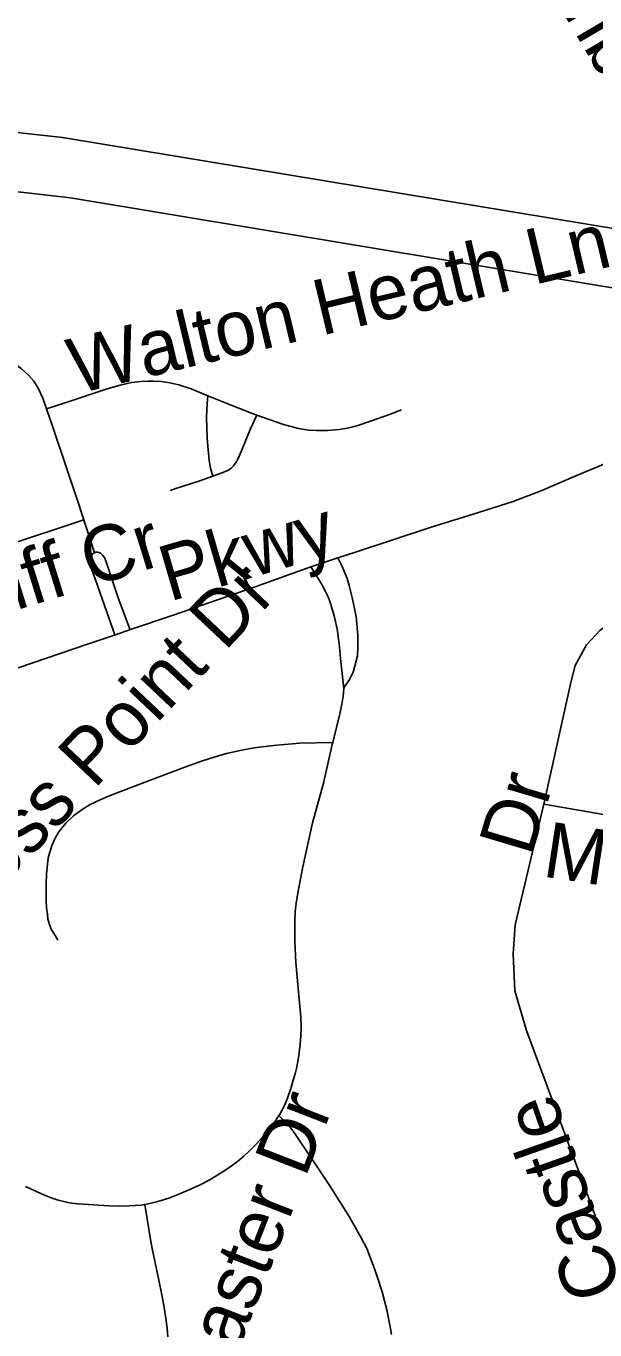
# Model space of a CAD drawing. Extents: x 1383679 to 1536984, y 460658 to 651027.
# Drawn here: x 1460933 to 1461906, y 480927 to 483158 of the extents above; entities that cross this region are included whole.
import ezdxf

# ---------------------------------------------------------------- set-up
doc = ezdxf.new("R2010")
doc.units = 0
for name, color, linetype in [('Exist Road Non-System Type 51', 7, 'Continuous'), ('Exist Road Non-System Type 51 Label', 7, 'Continuous'), ('Exist Road Primary Interstate Divided Center Attributed', 7, 'Continuous'), ('Exist Road Secondary Type 51 Attributed', 7, 'Continuous'), ('Exist Road Secondary Type 51 Label', 7, 'Continuous')]:
    doc.layers.add(name, color=color, linetype=linetype)

msp = doc.modelspace()

# ---------------------------------------------------------------- linework, layer by layer
at = {"layer": 'Exist Road Non-System Type 51'}
for points in [[(1460967.8, 482502.9), (1460961.4, 482521.3), (1460953.6, 482538.2), (1460945.8, 482550.2), (1460936.8, 482560.8), (1460925.1, 482571.5), (1460913.4, 482580.1), (1460905.8, 482584.1), (1460896.8, 482587.9), (1460886.4, 482591.3), (1460871.3, 482595), (1460845.3, 482600.2), (1460804.4, 482606.4), (1460775.1, 482610.2), (1460755.7, 482611.3), (1460740.7, 482610.6), (1460722.6, 482608.3), (1460702.6, 482604.4), (1460682.3, 482598.9), (1460672.8, 482594.4)], [(1461243.8, 482525.5), (1461226, 482532.8), (1461215.4, 482537.2), (1461194.2, 482543.9), (1461178.8, 482547.5), (1461163.7, 482549.8), (1461150.7, 482550.5), (1461141, 482550.6), (1461129.5, 482549.9), (1461113.2, 482547.8), (1461093.9, 482543.6), (1461073.5, 482538), (1460999.4, 482513.5), (1460967.8, 482502.9)], [(1461252.1, 482387.8), (1461248.4, 482401.7), (1461246.2, 482414.8), (1461243.6, 482439.3), (1461242.9, 482453.1), (1461241.8, 482488.5), (1461242.8, 482512.2), (1461243.8, 482525.5)], [(1461327.6, 482492.3), (1461321.2, 482494.5), (1461278.2, 482511.3), (1461243.8, 482525.5)], [(1461049.7, 482256.6), (1461021.7, 482342.8), (1460978.5, 482471.7), (1460967.8, 482502.9)], [(1461327.6, 482492.3), (1461316, 482467.5), (1461301.7, 482431.3), (1461294.9, 482416.6), (1461290.9, 482410), (1461287.2, 482405.1), (1461283.5, 482401.3), (1461279, 482398.2), (1461272.6, 482395.2), (1461252.1, 482387.8)], [(1461575.2, 482501.2), (1461554.7, 482493.5), (1461522.3, 482481.7), (1461500.7, 482474.7), (1461491.7, 482471.9), (1461482.9, 482469.9), (1461468.8, 482467.6), (1461448.6, 482465.9), (1461429.8, 482465.9), (1461415.9, 482466.5), (1461398.9, 482469.4), (1461373.2, 482476.3), (1461327.6, 482492.3)], [(1461252.1, 482387.8), (1461228.6, 482379.4), (1461189.2, 482366.6), (1461179.3, 482363.3)], [(1461031.4, 482313), (1460999, 482302), (1460924.9, 482277.6), (1460872.1, 482261), (1460851.8, 482253.4)], [(1461049.7, 482256.6), (1461048.6, 482256.1), (1461047.8, 482255.5), (1461046.6, 482254.6), (1461045.4, 482253), (1461044.5, 482251.5), (1461043.5, 482249.3), (1461042.7, 482245.4), (1461042.2, 482241.1), (1461042.6, 482237.7), (1461045, 482229.4), (1461050.8, 482212.3), (1461067.1, 482166.4), (1461084.7, 482116.1)], [(1461110.8, 482124.9), (1461090.7, 482178.1), (1461068.2, 482246.2), (1461066.3, 482249.4), (1461064.2, 482252), (1461061.4, 482254.9), (1461060.1, 482256), (1461058.8, 482256.6), (1461057, 482257.1), (1461055.4, 482257.4), (1461053.8, 482257.5), (1461052.4, 482257.4), (1461050.9, 482257.1), (1461049.7, 482256.6)], [(1461476.6, 482025.6), (1461486.4, 482039.8), (1461492.5, 482052.6), (1461497.2, 482069.4), (1461499.8, 482080.1), (1461500.8, 482095.8), (1461500.6, 482115.7), (1461497.4, 482147.4), (1461490.6, 482180.1), (1461485.7, 482200.7), (1461482.1, 482212.4), (1461473.6, 482233.4), (1461466.3, 482247.8)], [(1461419.9, 482232.7), (1461432.6, 482212.4), (1461438.2, 482203.7), (1461441.4, 482198), (1461445.2, 482190.6), (1461448.5, 482183.4), (1461451.4, 482176.6), (1461454.1, 482168.4), (1461457.2, 482158.7), (1461460.1, 482148.5), (1461462.2, 482139.3), (1461463.9, 482131.2), (1461465.5, 482122.8), (1461467, 482112.6), (1461468.4, 482100.8), (1461469.7, 482089.6), (1461471.1, 482075.9), (1461476.7, 482024.2), (1461475.7, 482011.3), (1461473.4, 481997.4), (1461469.7, 481980.9), (1461457.6, 481932)], [(1461819.1, 481826.7), (1461865.1, 482034.8), (1461872.4, 482063.7), (1461891.9, 482099.3), (1461915.4, 482124.1), (1461936.5, 482140.3), (1461954.6, 482152.3), (1461974.1, 482158.4), (1461995.6, 482163.8), (1462030.5, 482162.4), (1462058.7, 482157.7), (1462276.8, 482075.1)], [(1461457.6, 481932), (1461401.4, 481930.8), (1461362.1, 481927.5), (1461322.6, 481922.7), (1461299.2, 481918.4), (1461275.8, 481913.2), (1461254.6, 481907.1), (1461234.5, 481900.3), (1461208.8, 481891.3), (1461148.7, 481868.9), (1461099.1, 481849.7), (1461073.6, 481840.2), (1461059.3, 481833.9), (1461042.2, 481825.8), (1461028.6, 481817.5), (1461014.7, 481807), (1461000.9, 481794.1), (1460988.8, 481778.8), (1460982.3, 481768.2), (1460977.5, 481756.9), (1460972.7, 481742.5), (1460970.7, 481734.5), (1460969.2, 481722.9), (1460967.9, 481707.3), (1460966.9, 481689.2), (1460967, 481661.3), (1460967.9, 481648.9), (1460969.2, 481637.9), (1460970.2, 481629.8), (1460973.2, 481618.5), (1460976.5, 481611.2), (1460982.3, 481601.6), (1460987.1, 481593.6)], [(1461457.6, 481932), (1461456.7, 481928.4), (1461441.5, 481862.6), (1461423.2, 481794.6), (1461406.5, 481719.1), (1461397.8, 481674.6), (1461394.8, 481657), (1461393.1, 481642.2), (1461392.6, 481626.3), (1461392.9, 481592), (1461394.7, 481555.3), (1461398.8, 481505.4), (1461402.7, 481461.8), (1461403.6, 481444.6), (1461403.2, 481430.1), (1461402.1, 481416.4), (1461400.1, 481400.8), (1461398.4, 481389.3), (1461395.3, 481374.2), (1461393.1, 481364.9), (1461390, 481353.8), (1461385.8, 481339.9), (1461380.2, 481323.3), (1461375.4, 481312), (1461370.7, 481301.9), (1461366.4, 481294.9), (1461365.4, 481293.4)], [(1461907.1, 481120.6), (1461789.1, 481438.9), (1461769.2, 481507), (1461766.2, 481570.5), (1461769.9, 481619.8), (1461819.1, 481826.7)], [(1461819.1, 481826.7), (1461967.4, 481800.8), (1462263.3, 481754.2)], [(1461365.4, 481293.4), (1461358.8, 481283.3), (1461351.3, 481273), (1461344.7, 481265), (1461338.2, 481256.9), (1461326.4, 481244.3), (1461314.5, 481232.7), (1461305.5, 481223.9), (1461294.4, 481214.6), (1461283.8, 481206.8), (1461271, 481198.3), (1461256.6, 481189), (1461246.1, 481183.2), (1461230.5, 481174.9), (1461214.1, 481167.3), (1461194, 481158.8), (1461176.8, 481152.2), (1461164, 481148.2), (1461156.2, 481145.9), (1461146.7, 481143.3), (1461138.6, 481141.7), (1461135.9, 481141.2)], [(1461365.4, 481293.4), (1461382.4, 481276.7), (1461392.5, 481262.9), (1461452.7, 481173.4), (1461485.9, 481120.5), (1461506.2, 481084.4), (1461515.7, 481066), (1461526.6, 481037.4), (1461534.4, 481016.3), (1461542.2, 480992), (1461550.1, 480961), (1461556.1, 480932.2), (1461558.1, 480918.7)], [(1461135.9, 481141.2), (1461130.3, 481140.2), (1461119.7, 481139.4), (1461109.9, 481139.1), (1461091.8, 481138.6), (1461075.2, 481139.1), (1461056.8, 481139.9), (1461030.9, 481141.7), (1461020.8, 481142.4), (1461006.7, 481144.4), (1460997.4, 481146.2), (1460987.6, 481148.7), (1460977.5, 481152.2), (1460964.4, 481157.5), (1460931.8, 481172.3)], [(1461135.9, 481141.2), (1461145, 481084.6), (1461148.7, 481066), (1461159.5, 481014.9), (1461165.8, 480983.7), (1461169.1, 480965), (1461172.1, 480946.1), (1461174.4, 480929.5), (1461175.2, 480914.6)]]:
    msp.add_lwpolyline(points, dxfattribs=at)
at = {"layer": 'Exist Road Primary Interstate Divided Center Attributed'}
for points in [[(1462470, 482723.8), (1460995.2, 482967.2), (1459214, 483163.4), (1458773.1, 483198.7), (1458336.5, 483234.1), (1458156.8, 483240.7)], [(1458190, 483136.4), (1458674, 483131), (1461008.7, 482864.3), (1463176.2, 482504.4), (1464881.1, 482241.3), (1465669.4, 482116.9), (1466817.1, 481926.4), (1467830.4, 481763.9), (1468861.2, 481599.9)]]:
    msp.add_lwpolyline(points, dxfattribs=at)
at = {"layer": 'Exist Road Secondary Type 51 Attributed'}
for p, q in [((1461466.3, 482247.8), (1461419.9, 482232.7)), ((1461111.5, 482125.1), (1461085.6, 482116.4))]:
    msp.add_line(p, q, dxfattribs=at)
for points in [[(1462020.9, 482456.9), (1461991.3, 482442.2), (1461948.6, 482421.9), (1461917.3, 482406.7), (1461873.6, 482388.5), (1461815.3, 482363.3), (1461766.2, 482344.4), (1461706.9, 482325.4), (1461624.4, 482299.9), (1461498, 482258.1), (1461466.3, 482247.8)], [(1461419.9, 482232.7), (1461324.7, 482198.1), (1461184.4, 482149.7), (1461111.5, 482125.1)], [(1461085.6, 482116.4), (1461036.4, 482099.9), (1460827, 482028.4), (1460597.2, 481949.9), (1460506.1, 481919.8), (1460303.2, 481853.2), (1460125.7, 481792.9), (1459950.5, 481735), (1459913.9, 481724)]]:
    msp.add_lwpolyline(points, dxfattribs=at)

# ---------------------------------------------------------------- texts
at = {"layer": 'Exist Road Non-System Type 51 Label'}
for s, rotation, p in [('Brambleton Ct', 300.4411, (1461731.5, 483385.1)), ('Walton Heath Ln', 13.4254, (1461018.7, 482528)), ('Baniff Cr', 17.2798, (1460699.7, 482090.8)), ('Moss Point Dr', 46.5695, (1460816.4, 481604.8)), ('Dr', 73.3885, (1461797.5, 481734.8)), ('Morgana', 351.2916, (1461814.5, 481703)), ('Huntsmaster Dr', 68.7417, (1461136.6, 480481.5)), ('Castle', 109.3517, (1461954, 480997))]:
    msp.add_text(s, height=95, rotation=rotation, dxfattribs=at).set_placement(p)
at = {"layer": 'Exist Road Secondary Type 51 Label'}
msp.add_text('Pkwy', height=95, rotation=16.247, dxfattribs=at).set_placement((1461177.9, 482172.7))

doc.saveas('drawing.dxf')
